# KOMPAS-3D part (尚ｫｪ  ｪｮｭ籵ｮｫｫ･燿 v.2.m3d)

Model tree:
1. Эскиз:1
2. Операция выдавливания:1
     Расстояние 1 = 2
3. Эскиз:3
4. Вырезать элемент выдавливания:3  (labels: Текстолит ГОСТ 5-78; SYSTEM_PROPERTY_ADDITIONAL_FOR:9.000000)
     Расстояние 1 = 2

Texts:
  Текстолит ГОСТ 5-78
